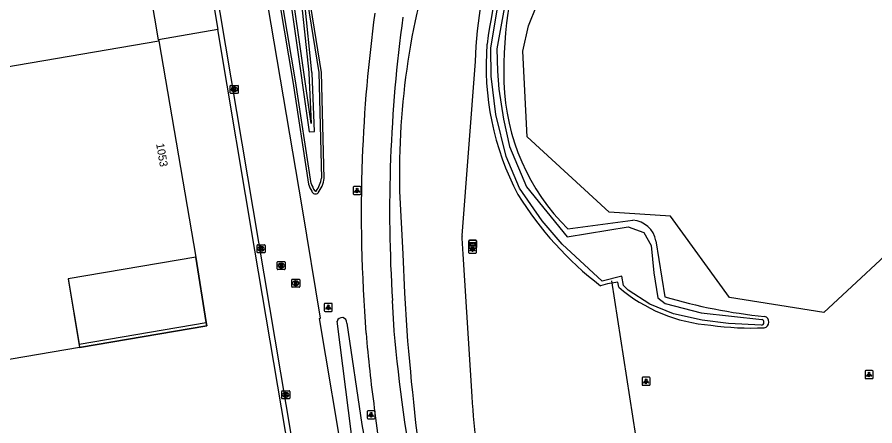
# Model space of a CAD drawing. Extents: x 154324 to 155743, y 382939 to 384183.
# Drawn here: x 154972.4 to 155079.5, y 383769.7 to 383820.7 of the extents above; entities that cross this region are included whole.
import ezdxf

# ---------------------------------------------------------------- set-up
doc = ezdxf.new("R2010")
doc.units = 0
for name, color, linetype in [('IMGEO_Duiker', 7, 'Continuous'), ('IMGEO_Erf', 7, 'Continuous'), ('IMGEO_Fietspad_gesloten', 7, 'Continuous'), ('IMGEO_Gemengd_bos', 7, 'Continuous'), ('IMGEO_Groenvoorziening', 7, 'Continuous'), ('IMGEO_Kolk', 7, 'Continuous'), ('IMGEO_Lichtpunt', 7, 'Continuous'), ('IMGEO_Loofbos', 7, 'Continuous'), ('IMGEO_Muur', 7, 'Continuous'), ('IMGEO_Pand', 7, 'Continuous'), ('IMGEO_Pand_nummerreeks', 7, 'Continuous'), ('IMGEO_Pand_overbouw', 7, 'Continuous'), ('IMGEO_Rijbaan_lokaal_gesloten', 7, 'Continuous'), ('IMGEO_Rijbaan_lokaal_open', 7, 'Continuous'), ('IMGEO_Rijbaan_regionaal_gesloten', 7, 'Continuous'), ('IMGEO_Rioolput', 7, 'Continuous'), ('IMGEO_Voetpad_open', 7, 'Continuous'), ('IMGEO_Waterloop', 7, 'Continuous'), ('IMGEO_Wegwijzer', 7, 'Continuous')]:
    doc.layers.add(name, color=color, linetype=linetype)

msp = doc.modelspace()

# ---------------------------------------------------------------- linework, layer by layer
at = {"layer": 'IMGEO_Duiker'}
msp.add_lwpolyline([(155049.67, 383768.43), (155046.67, 383787.76)], dxfattribs=at)
at = {"layer": 'IMGEO_Erf'}
msp.add_lwpolyline([(154994.7, 383790.75), (154996.01, 383782.59)], dxfattribs=at)
at = {"layer": 'IMGEO_Fietspad_gesloten'}
for points in [[(155019.46, 383781.51), (155019.26, 383785.32)], [(155017, 383771.86), (155017.48, 383768.13), (155017.91, 383765.01), (155017.96, 383764.73)]]:
    msp.add_lwpolyline(points, dxfattribs=at)
for centre, radius, start, end in [((155201.03, 383796.14), 185.67, 172.2319, 177.8658), ((155196.34, 383796.49), 177.43, 172.1463, 183.611), ((155203.95, 383796.15), 188.58, 177.9006, 184.5318), ((155202.2, 383797.06), 186.91, 184.8539, 187.7502), ((155254.72, 383803.12), 236.26, 185.2489, 190.1997)]:
    msp.add_arc(centre, radius, start, end, dxfattribs=at)
at = {"layer": 'IMGEO_Gemengd_bos'}
msp.add_lwpolyline([(154998.88, 383878.34), (155000.01, 383871.99), (155007.92, 383822.41), (155008.83, 383813.83), (155008.83, 383813.73), (155009.11, 383807.44), (155005.61, 383831.96), (154997.58, 383876.45)], dxfattribs=at)
at = {"layer": 'IMGEO_Groenvoorziening'}
for points in [[(155010.75, 383800.59), (155010.4, 383813.83), (154999.78, 383879.59)], [(154996.53, 383874.02), (154997.02, 383870.74), (155006.82, 383812.7), (155008.78, 383799.87)], [(155041.18, 383794.28), (155049.3, 383795.38)], [(155052.18, 383792.79), (155053.29, 383785.8)], [(155047.53, 383786.99), (155047.42, 383787.62), (155046.12, 383787.4), (155045.26, 383787.17)]]:
    msp.add_lwpolyline(points, dxfattribs=at)
for centre, radius, start, end in [((155120.8, 383804.78), 90.6, 161.2609, 172.0095), ((155084.94, 383813.98), 51.77, 159.536, 181.587), ((155065.28, 383814.6), 34.32, 175.3553, 207.8429), ((155059.99, 383813.39), 26.82, 181.7899, 225.4537), ((155006.28, 383801.38), 4.54, 324.7543, 349.957), ((155012.45, 383801.01), 3.84, 197.2177, 211.5913), ((155009.66, 383799.14), 0.506, 197.1336, 310.2482), ((155071, 383820.82), 42.37, 211.6754, 232.5903), ((155049.01, 383792.16), 3.23, 11.2316, 84.8446), ((155060.52, 383802.14), 19.96, 229.394, 265.7316), ((155072.34, 383849.36), 66.36, 253.3152, 264.2951), ((155065.56, 383782.63), 0.73, 282.1039, 75.4773), ((155064.17, 383819.35), 37.47, 262.1225, 272.3514)]:
    msp.add_arc(centre, radius, start, end, dxfattribs=at)
at = {"layer": 'IMGEO_Kolk'}
for p, q in [((154999.01, 383811.28), (154999.01, 383812.14)), ((154999.08, 383812.21), (154999.93, 383812.21)), ((154999.49, 383811.99), (154999.52, 383811.99)), ((155000.01, 383812.14), (155000.01, 383811.28)), ((154999.93, 383811.21), (154999.08, 383811.21)), ((154999.52, 383811.43), (154999.49, 383811.43)), ((155002.36, 383791.36), (155002.36, 383792.21)), ((155002.43, 383792.29), (155003.28, 383792.29)), ((155002.87, 383791.51), (155002.84, 383791.51)), ((155002.85, 383792.06), (155002.87, 383792.06)), ((155003.36, 383792.21), (155003.36, 383791.36)), ((155003.28, 383791.28), (155002.43, 383791.28)), ((155005.44, 383773.11), (155005.44, 383773.96)), ((155005.51, 383774.04), (155006.36, 383774.04)), ((155005.95, 383773.26), (155005.92, 383773.26)), ((155005.93, 383773.81), (155005.95, 383773.81)), ((155006.44, 383773.96), (155006.44, 383773.11)), ((155006.36, 383773.03), (155005.51, 383773.03))]:
    msp.add_line(p, q, dxfattribs=at)
for points in [[(154999.01, 383811.28), (154999.01, 383812.14)], [(154999.08, 383812.21), (154999.93, 383812.21)], [(154999.33, 383811.91), (154999.45, 383811.91), (154999.45, 383811.76), (154999.58, 383811.91), (154999.74, 383811.91), (154999.6, 383811.76), (154999.75, 383811.51), (154999.6, 383811.51), (154999.51, 383811.68), (154999.45, 383811.61), (154999.45, 383811.51), (154999.33, 383811.51), (154999.33, 383811.91)], [(155000.01, 383812.14), (155000.01, 383811.28)], [(154999.93, 383811.21), (154999.08, 383811.21)], [(155002.36, 383791.36), (155002.36, 383792.21)], [(155002.43, 383792.29), (155003.28, 383792.29)], [(155002.68, 383791.98), (155002.8, 383791.98), (155002.8, 383791.83), (155002.93, 383791.98), (155003.1, 383791.98), (155002.95, 383791.83), (155003.1, 383791.58), (155002.95, 383791.58), (155002.87, 383791.75), (155002.8, 383791.68), (155002.8, 383791.58), (155002.68, 383791.58), (155002.68, 383791.98)], [(155003.36, 383792.21), (155003.36, 383791.36)], [(155003.28, 383791.28), (155002.43, 383791.28)], [(155005.44, 383773.11), (155005.44, 383773.96)], [(155005.51, 383774.04), (155006.36, 383774.04)], [(155005.76, 383773.73), (155005.88, 383773.73), (155005.88, 383773.58), (155006.01, 383773.73), (155006.18, 383773.73), (155006.03, 383773.58), (155006.18, 383773.33), (155006.03, 383773.33), (155005.95, 383773.5), (155005.88, 383773.43), (155005.88, 383773.33), (155005.76, 383773.33), (155005.76, 383773.73)], [(155006.44, 383773.96), (155006.44, 383773.11)], [(155006.36, 383773.03), (155005.51, 383773.03)]]:
    msp.add_lwpolyline(points, dxfattribs=at)
for centre, start, end in [((154999.08, 383812.14), 91.552, 178.448), ((154999.08, 383812.14), 91.552, 178.448), ((154999.93, 383812.14), 1.552, 88.448), ((154999.93, 383812.14), 1.552, 88.448), ((154999.08, 383811.29), 181.552, 268.448), ((154999.08, 383811.29), 181.552, 268.448), ((154999.93, 383811.29), 271.552, 358.448), ((154999.93, 383811.29), 271.552, 358.448), ((155002.43, 383792.21), 91.552, 178.448), ((155002.43, 383792.21), 91.552, 178.448), ((155003.28, 383792.21), 1.552, 88.448), ((155003.28, 383792.21), 1.552, 88.448), ((155002.43, 383791.36), 181.552, 268.448), ((155002.43, 383791.36), 181.552, 268.448), ((155003.28, 383791.36), 271.552, 358.448), ((155003.28, 383791.36), 271.552, 358.448), ((155005.51, 383773.96), 91.552, 178.448), ((155005.51, 383773.96), 91.552, 178.448), ((155006.36, 383773.96), 1.552, 88.448), ((155006.36, 383773.96), 1.552, 88.448), ((155005.51, 383773.11), 181.552, 268.448), ((155005.51, 383773.11), 181.552, 268.448), ((155006.36, 383773.11), 271.552, 358.448), ((155006.36, 383773.11), 271.552, 358.448)]:
    msp.add_arc(centre, 0.0765, start, end, dxfattribs=at)
for centre, major_axis, ratio, start_param, end_param in [((154999.49, 383811.71), (-0.387, 0.002), 0.722429, 4.712389, 7.853982), ((154999.52, 383811.71), (-0.39, 0.002), 0.717154, 1.570796, 4.712389), ((155002.84, 383791.78), (-0.387, 0.002), 0.722429, 4.712389, 7.853982), ((155002.87, 383791.78), (-0.39, 0.002), 0.717154, 1.570796, 4.712389), ((155005.92, 383773.53), (-0.387, 0.002), 0.722429, 4.712389, 7.853982), ((155005.95, 383773.53), (-0.39, 0.002), 0.717154, 1.570796, 4.712389)]:
    msp.add_ellipse(centre, major_axis=major_axis, ratio=ratio, start_param=start_param, end_param=end_param, dxfattribs=at)
at = {"layer": 'IMGEO_Lichtpunt'}
for p, q in [((155014.35, 383799.47), (155014.35, 383798.66)), ((155014.35, 383799.47), (155014.35, 383798.66)), ((155015.25, 383799.56), (155014.45, 383799.56)), ((155015.25, 383799.56), (155014.45, 383799.56)), ((155015.35, 383798.66), (155015.35, 383799.47)), ((155015.35, 383798.66), (155015.35, 383799.47)), ((155014.45, 383798.57), (155015.25, 383798.57)), ((155014.45, 383798.57), (155015.25, 383798.57)), ((155028.77, 383792.14), (155028.77, 383791.33)), ((155028.77, 383792.14), (155028.77, 383791.33)), ((155029.67, 383792.23), (155028.86, 383792.23)), ((155029.67, 383792.23), (155028.86, 383792.23)), ((155029.76, 383791.33), (155029.76, 383792.14)), ((155029.76, 383791.33), (155029.76, 383792.14)), ((155028.86, 383791.23), (155029.67, 383791.23)), ((155028.86, 383791.23), (155029.67, 383791.23)), ((155010.75, 383784.87), (155010.75, 383784.06)), ((155010.75, 383784.87), (155010.75, 383784.06)), ((155011.65, 383784.96), (155010.85, 383784.96)), ((155011.65, 383784.96), (155010.85, 383784.96)), ((155010.85, 383783.96), (155011.65, 383783.96)), ((155010.85, 383783.96), (155011.65, 383783.96)), ((155011.75, 383784.06), (155011.75, 383784.87)), ((155011.75, 383784.06), (155011.75, 383784.87)), ((155078.3, 383776.47), (155078.3, 383775.66)), ((155078.3, 383776.47), (155078.3, 383775.66)), ((155079.2, 383776.57), (155078.39, 383776.57)), ((155079.2, 383776.57), (155078.39, 383776.57)), ((155079.3, 383775.66), (155079.3, 383776.47)), ((155079.3, 383775.66), (155079.3, 383776.47)), ((155050.45, 383775.63), (155050.45, 383774.82)), ((155050.45, 383775.63), (155050.45, 383774.82)), ((155051.35, 383775.72), (155050.54, 383775.72)), ((155051.35, 383775.72), (155050.54, 383775.72)), ((155051.44, 383774.82), (155051.44, 383775.63)), ((155051.44, 383774.82), (155051.44, 383775.63)), ((155078.39, 383775.57), (155079.2, 383775.57)), ((155078.39, 383775.57), (155079.2, 383775.57)), ((155050.54, 383774.72), (155051.35, 383774.72)), ((155050.54, 383774.72), (155051.35, 383774.72)), ((155016.1, 383771.44), (155016.1, 383770.64)), ((155016.1, 383771.44), (155016.1, 383770.64)), ((155017, 383771.54), (155016.2, 383771.54)), ((155017, 383771.54), (155016.2, 383771.54)), ((155017.1, 383770.64), (155017.1, 383771.44)), ((155017.1, 383770.64), (155017.1, 383771.44)), ((155016.2, 383770.54), (155017, 383770.54)), ((155016.2, 383770.54), (155017, 383770.54))]:
    msp.add_line(p, q, dxfattribs=at)
for points in [[(155014.73, 383799.13), (155014.76, 383799.1), (155014.58, 383798.84), (155014.54, 383798.87), (155014.73, 383799.13)], [(155014.83, 383799.08), (155014.87, 383799.08), (155014.87, 383798.76), (155014.83, 383798.76), (155014.83, 383799.08)], [(155014.94, 383799.1), (155014.98, 383799.13), (155015.16, 383798.87), (155015.12, 383798.84), (155014.94, 383799.1)], [(155029.14, 383791.8), (155029.18, 383791.77), (155028.99, 383791.51), (155028.95, 383791.54), (155029.14, 383791.8)], [(155029.24, 383791.75), (155029.29, 383791.75), (155029.29, 383791.43), (155029.24, 383791.43), (155029.24, 383791.75)], [(155029.35, 383791.77), (155029.39, 383791.8), (155029.58, 383791.54), (155029.54, 383791.51), (155029.35, 383791.77)], [(155011.13, 383784.53), (155011.16, 383784.5), (155010.98, 383784.24), (155010.94, 383784.27), (155011.13, 383784.53)], [(155011.23, 383784.48), (155011.27, 383784.48), (155011.27, 383784.16), (155011.23, 383784.16), (155011.23, 383784.48)], [(155011.34, 383784.5), (155011.38, 383784.53), (155011.56, 383784.27), (155011.52, 383784.24), (155011.34, 383784.5)], [(155078.67, 383776.13), (155078.71, 383776.11), (155078.53, 383775.84), (155078.49, 383775.87), (155078.67, 383776.13)], [(155078.78, 383776.09), (155078.82, 383776.09), (155078.82, 383775.76), (155078.78, 383775.76), (155078.78, 383776.09)], [(155078.89, 383776.11), (155078.92, 383776.13), (155079.11, 383775.87), (155079.07, 383775.84), (155078.89, 383776.11)], [(155050.82, 383775.29), (155050.86, 383775.26), (155050.67, 383775), (155050.63, 383775.03), (155050.82, 383775.29)], [(155050.92, 383775.24), (155050.97, 383775.24), (155050.97, 383774.92), (155050.92, 383774.92), (155050.92, 383775.24)], [(155051.03, 383775.26), (155051.07, 383775.29), (155051.26, 383775.03), (155051.22, 383775), (155051.03, 383775.26)], [(155016.48, 383771.11), (155016.52, 383771.08), (155016.33, 383770.82), (155016.29, 383770.85), (155016.48, 383771.11)], [(155016.58, 383771.06), (155016.63, 383771.06), (155016.63, 383770.74), (155016.58, 383770.74), (155016.58, 383771.06)], [(155016.69, 383771.08), (155016.73, 383771.11), (155016.91, 383770.84), (155016.88, 383770.82), (155016.69, 383771.08)]]:
    msp.add_lwpolyline(points, dxfattribs=at)
for centre in [(155014.85, 383799.27), (155029.27, 383791.93), (155011.25, 383784.66), (155050.95, 383775.42), (155078.8, 383776.27), (155016.6, 383771.24)]:
    msp.add_circle(centre, 0.0994, dxfattribs=at)
for centre, start, end in [((155014.45, 383799.47), 90, 180), ((155014.45, 383799.47), 90, 180), ((155015.25, 383799.47), 0, 90), ((155015.25, 383799.47), 0, 90), ((155014.45, 383798.66), 180, 270), ((155014.45, 383798.66), 180, 270), ((155015.25, 383798.66), 270, 0), ((155015.25, 383798.66), 270, 360), ((155028.86, 383792.14), 90, 180), ((155028.86, 383792.14), 90, 180), ((155029.67, 383792.14), 0, 90), ((155029.67, 383792.14), 0, 90), ((155028.86, 383791.33), 180, 270), ((155028.86, 383791.33), 180, 270), ((155029.67, 383791.33), 270, 0), ((155029.67, 383791.33), 270, 360), ((155010.85, 383784.87), 90, 180), ((155010.85, 383784.87), 90, 180), ((155010.85, 383784.06), 180, 270), ((155010.85, 383784.06), 180, 270), ((155011.65, 383784.87), 0, 90), ((155011.65, 383784.87), 0, 90), ((155011.65, 383784.06), 270, 0), ((155011.65, 383784.06), 270, 360), ((155078.39, 383776.47), 90, 180), ((155078.39, 383776.47), 90, 180), ((155079.2, 383776.47), 0, 90), ((155079.2, 383776.47), 0, 90), ((155050.54, 383775.63), 90, 180), ((155050.54, 383775.63), 90, 180), ((155051.35, 383775.63), 0, 90), ((155051.35, 383775.63), 0, 90), ((155078.39, 383775.66), 180, 270), ((155078.39, 383775.66), 180, 270), ((155079.2, 383775.66), 270, 0), ((155079.2, 383775.66), 270, 360), ((155050.54, 383774.82), 180, 270), ((155050.54, 383774.82), 180, 270), ((155051.35, 383774.82), 270, 0), ((155051.35, 383774.82), 270, 360), ((155016.2, 383771.44), 90, 180), ((155016.2, 383771.44), 90, 180), ((155017, 383771.44), 0, 90), ((155017, 383771.44), 0, 90), ((155016.2, 383770.64), 180, 270), ((155016.2, 383770.64), 180, 270), ((155017, 383770.64), 270, 0), ((155017, 383770.64), 270, 360)]:
    msp.add_arc(centre, 0.0946, start, end, dxfattribs=at)
at = {"layer": 'IMGEO_Loofbos'}
msp.add_lwpolyline([(155084.25, 383794.14), (155073.15, 383783.84), (155061.37, 383785.71), (155054, 383795.85), (155046.34, 383796.37), (155036.09, 383805.76), (155035.55, 383816.5), (155036.27, 383819.67), (155039.4, 383827.45), (155039.85, 383836.79), (155046.95, 383856.23), (155051.31, 383866.25), (155057.27, 383876.68), (155066.29, 383893.02), (155069.68, 383892.75), (155069.28, 383874.53), (155080.69, 383874.83)], dxfattribs=at)
at = {"layer": 'IMGEO_Muur'}
for points in [[(154980.12, 383779.88), (154996.01, 383782.59)], [(154996.01, 383782.59), (154996.08, 383782.15), (154980.19, 383779.45)]]:
    msp.add_lwpolyline(points, dxfattribs=at)
at = {"layer": 'IMGEO_Pand'}
for points in [[(154990.05, 383817.92), (154983.07, 383859.06), (154983.42, 383859.11), (154983.38, 383859.35), (154982.28, 383859.17), (154981.76, 383862.33), (154982.84, 383862.51), (154982.8, 383862.75), (154982.45, 383862.69)], [(154925.99, 383806.82), (154990.08, 383817.77)], [(154990.05, 383817.92), (154990.08, 383817.77)], [(154990.08, 383817.77), (154994.7, 383790.75)], [(154980.19, 383779.45), (154932.1, 383771.26), (154925.99, 383806.82)], [(154994.7, 383790.75), (154978.75, 383788.05), (154980.12, 383779.88)], [(154980.12, 383779.88), (154980.19, 383779.45)]]:
    msp.add_lwpolyline(points, dxfattribs=at)
at = {"layer": 'IMGEO_Pand_overbouw'}
msp.add_lwpolyline([(154994.7, 383790.75), (154978.75, 383788.05), (154980.19, 383779.45), (154996.08, 383782.15), (154996.01, 383782.59)], close=True, dxfattribs=at)
at = {"layer": 'IMGEO_Rijbaan_lokaal_gesloten'}
for points in [[(154990.18, 383866.13), (155008.69, 383756)], [(155013.37, 383763.97), (155010.14, 383783.07), (155010.29, 383783.1), (155007.98, 383797.02), (155002.17, 383831.43), (154996.94, 383862.79)]]:
    msp.add_lwpolyline(points, dxfattribs=at)
at = {"layer": 'IMGEO_Rijbaan_lokaal_open'}
for points in [[(154989.69, 383865.49), (154997.46, 383819.18)], [(155016.28, 383707.11), (155013.83, 383721.66), (155012.36, 383730.43), (155011.19, 383737.43), (155008.64, 383752.61), (155006.35, 383766.23), (155002.09, 383791.61), (154997.46, 383819.18)]]:
    msp.add_lwpolyline(points, dxfattribs=at)
at = {"layer": 'IMGEO_Rijbaan_regionaal_gesloten'}
for points in [[(155029.61, 383815.18), (155027.95, 383793.43)], [(155020.16, 383798.97), (155020.54, 383791.13), (155020.78, 383786.3), (155021.06, 383781.53)], [(155027.91, 383793.13), (155028.04, 383791.11), (155029.16, 383773.33)]]:
    msp.add_lwpolyline(points, dxfattribs=at)
for centre, radius, start, end in [((155112.77, 383801.26), 92.64, 161.2191, 181.4184), ((155074.66, 383814.46), 45.05, 159.4575, 179.0818), ((155028.85, 383793.14), 0.939, 162.3667, 180.8351), ((155354.04, 383807.72), 334.01, 184.4973, 188.0146), ((155192.44, 383784.76), 163.68, 184.0042, 188.6495)]:
    msp.add_arc(centre, radius, start, end, dxfattribs=at)
at = {"layer": 'IMGEO_Rioolput'}
for p, q in [((155004.86, 383789.26), (155004.86, 383790.12)), ((155004.93, 383790.19), (155005.79, 383790.19)), ((155005.35, 383789.97), (155005.37, 383789.97)), ((155005.37, 383789.41), (155005.35, 383789.41)), ((155005.86, 383790.12), (155005.86, 383789.26)), ((155005.79, 383789.19), (155004.93, 383789.19)), ((155006.68, 383787.06), (155006.68, 383787.91)), ((155006.75, 383787.98), (155007.61, 383787.98)), ((155007.19, 383787.2), (155007.16, 383787.2)), ((155007.17, 383787.76), (155007.19, 383787.76)), ((155007.68, 383787.91), (155007.68, 383787.06)), ((155007.61, 383786.98), (155006.75, 383786.98))]:
    msp.add_line(p, q, dxfattribs=at)
for points in [[(155004.86, 383789.26), (155004.86, 383790.12)], [(155004.93, 383790.19), (155005.79, 383790.19)], [(155005.45, 383789.89), (155005.2, 383789.89), (155005.2, 383789.49)], [(155005.2, 383789.49), (155005.32, 383789.49), (155005.32, 383789.65), (155005.33, 383789.65)], [(155005.38, 383789.81), (155005.32, 383789.81), (155005.32, 383789.73)], [(155005.32, 383789.73), (155005.37, 383789.73)], [(155005.38, 383789.62), (155005.45, 383789.49), (155005.59, 383789.49), (155005.52, 383789.62)], [(155005.86, 383790.12), (155005.86, 383789.26)], [(155005.79, 383789.19), (155004.93, 383789.19)], [(155006.68, 383787.06), (155006.68, 383787.91)], [(155006.75, 383787.98), (155007.61, 383787.98)], [(155007.27, 383787.68), (155007.02, 383787.68), (155007.02, 383787.28)], [(155007.02, 383787.28), (155007.14, 383787.28), (155007.14, 383787.45), (155007.15, 383787.45)], [(155007.19, 383787.6), (155007.14, 383787.6), (155007.14, 383787.52)], [(155007.14, 383787.52), (155007.19, 383787.52)], [(155007.2, 383787.42), (155007.27, 383787.28), (155007.41, 383787.28), (155007.34, 383787.41)], [(155007.68, 383787.91), (155007.68, 383787.06)], [(155007.61, 383786.98), (155006.75, 383786.98)]]:
    msp.add_lwpolyline(points, dxfattribs=at)
for centre, radius, start, end in [((155004.94, 383790.12), 0.0765, 91.552, 178.448), ((155004.94, 383790.12), 0.0765, 91.552, 178.448), ((155004.94, 383789.27), 0.0765, 181.552, 268.448), ((155004.94, 383789.27), 0.0765, 181.552, 268.448), ((155005.33, 383789.6), 0.0533, 26.0293, 88.6989), ((155005.36, 383789.92), 0.19, 274.7715, 282.9687), ((155005.38, 383789.71), 0.0964, 77.0061, 93.1865), ((155005.4, 383789.77), 0.0378, 276.6634, 79.6772), ((155005.45, 383789.78), 0.109, 350.3612, 89.416), ((155005.45, 383789.78), 0.112, 277.5842, 350.9817), ((155005.43, 383789.56), 0.108, 29.5134, 73.7905), ((155005.78, 383790.12), 0.0765, 1.552, 88.448), ((155005.78, 383790.12), 0.0765, 1.552, 88.448), ((155005.78, 383789.27), 0.0765, 271.552, 358.448), ((155005.78, 383789.27), 0.0765, 271.552, 358.448), ((155006.76, 383787.91), 0.0765, 91.552, 178.448), ((155006.76, 383787.91), 0.0765, 91.552, 178.448), ((155007.15, 383787.39), 0.0533, 26.0293, 88.6989), ((155007.2, 383787.51), 0.0964, 77.0061, 93.1865), ((155007.18, 383787.71), 0.19, 274.7715, 282.9687), ((155007.21, 383787.56), 0.0378, 276.6634, 79.6772), ((155007.27, 383787.57), 0.109, 350.3612, 89.416), ((155007.27, 383787.57), 0.112, 277.5842, 350.9817), ((155007.25, 383787.36), 0.108, 29.5134, 73.7905), ((155007.6, 383787.91), 0.0765, 1.552, 88.448), ((155007.6, 383787.91), 0.0765, 1.552, 88.448), ((155006.76, 383787.06), 0.0765, 181.552, 268.448), ((155006.76, 383787.06), 0.0765, 181.552, 268.448), ((155007.6, 383787.06), 0.0765, 271.552, 358.448), ((155007.6, 383787.06), 0.0765, 271.552, 358.448)]:
    msp.add_arc(centre, radius, start, end, dxfattribs=at)
for centre, major_axis, ratio, start_param, end_param in [((155005.35, 383789.69), (-0.387, 0.002), 0.722429, 4.712389, 7.853982), ((155005.37, 383789.69), (-0.39, 0.002), 0.717154, 1.570796, 4.712389), ((155007.17, 383787.48), (-0.387, 0.002), 0.722429, 4.712389, 7.853982), ((155007.19, 383787.48), (-0.39, 0.002), 0.717154, 1.570796, 4.712389)]:
    msp.add_ellipse(centre, major_axis=major_axis, ratio=ratio, start_param=start_param, end_param=end_param, dxfattribs=at)
at = {"layer": 'IMGEO_Voetpad_open'}
msp.add_lwpolyline([(154997.46, 383819.18), (154990.05, 383817.92)], dxfattribs=at)
at = {"layer": 'IMGEO_Waterloop'}
for points in [[(154997.28, 383875.91), (155005.23, 383831.9), (155008.87, 383806.4), (155009.54, 383806.43), (155009.22, 383813.75), (155009.21, 383813.87), (155008.3, 383822.46), (155000.39, 383872.06), (154999.2, 383878.78)], [(154999.5, 383879.2), (155000.84, 383870.94), (155010.07, 383813.8), (155010.41, 383800.61)], [(155009.11, 383799.95), (155007.16, 383812.76), (154997.36, 383870.79), (154996.76, 383874.72)], [(155033.65, 383824.17), (155032.29, 383816.76), (155032.4, 383813.98), (155032.55, 383811.73), (155033.14, 383807.97), (155033.9, 383804.55), (155035.99, 383799.54), (155041.1, 383793.3), (155048.72, 383794.55), (155050.66, 383793.81), (155051.59, 383792.19), (155051.93, 383788.8), (155052.4, 383785.65), (155053.33, 383784.93), (155057.83, 383783.79), (155065.42, 383782.96)], [(155065.36, 383782.22), (155061.22, 383782.44), (155057.93, 383782.86), (155054.36, 383783.65), (155051.43, 383784.88), (155048.71, 383786.62), (155048.12, 383787.19), (155047.93, 383788.36), (155045.44, 383787.72), (155040.45, 383792.37), (155037.95, 383795.26), (155035.12, 383799.37), (155033.47, 383803.33), (155032.17, 383808.58), (155031.58, 383813.38), (155031.54, 383816.89), (155032.6, 383823.17)], [(155015.42, 383769.82), (155016.43, 383764.41), (155015.09, 383764.12), (155014.16, 383768.6), (155012.36, 383782.72)], [(155013.55, 383782.5), (155015.42, 383769.82)]]:
    msp.add_lwpolyline(points, dxfattribs=at)
for centre, radius, start, end in [((155006.38, 383801.33), 4.09, 325.1656, 349.8317), ((155013.17, 383801.31), 4.28, 198.5266, 212.3666), ((155009.66, 383799.14), 0.166, 229.9446, 299.059), ((155012.95, 383782.58), 0.607, 352.2319, 167.15), ((155065.28, 383782.6), 0.39, 282.0751, 68.2318)]:
    msp.add_arc(centre, radius, start, end, dxfattribs=at)
at = {"layer": 'IMGEO_Wegwijzer'}
for p, q in [((155028.79, 383791.96), (155028.79, 383792.76)), ((155028.79, 383792.76), (155028.79, 383791.96)), ((155028.89, 383792.86), (155029.68, 383792.86)), ((155029.68, 383792.86), (155028.89, 383792.86)), ((155029.78, 383792.76), (155029.78, 383791.96)), ((155029.78, 383791.96), (155029.78, 383792.76)), ((155029.68, 383791.86), (155028.89, 383791.86)), ((155028.89, 383791.86), (155029.68, 383791.86))]:
    msp.add_line(p, q, dxfattribs=at)
for points in [[(155028.89, 383792.59), (155029.68, 383792.59), (155029.68, 383792.13), (155028.89, 383792.13), (155028.89, 383792.59)], [(155028.96, 383792.44), (155028.96, 383792.36), (155028.96, 383792.28), (155029.37, 383792.28), (155029.37, 383792.19), (155029.61, 383792.36), (155029.37, 383792.53), (155029.37, 383792.44), (155028.96, 383792.44)]]:
    msp.add_lwpolyline(points, dxfattribs=at)
for centre, start, end in [((155028.89, 383792.76), 90, 180), ((155028.89, 383792.76), 90, 180), ((155029.68, 383792.76), 0, 90), ((155029.68, 383792.76), 360, 90), ((155028.89, 383791.96), 180, 270), ((155028.89, 383791.96), 180, 270), ((155029.68, 383791.96), 270, 0), ((155029.68, 383791.96), 270, 0)]:
    msp.add_arc(centre, 0.1, start, end, dxfattribs=at)

# ---------------------------------------------------------------- texts
at = {"layer": 'IMGEO_Pand_nummerreeks'}
msp.add_text('1053', height=1, rotation=279.7, dxfattribs=at).set_placement((154989.74, 383804.9))

doc.saveas('drawing.dxf')
